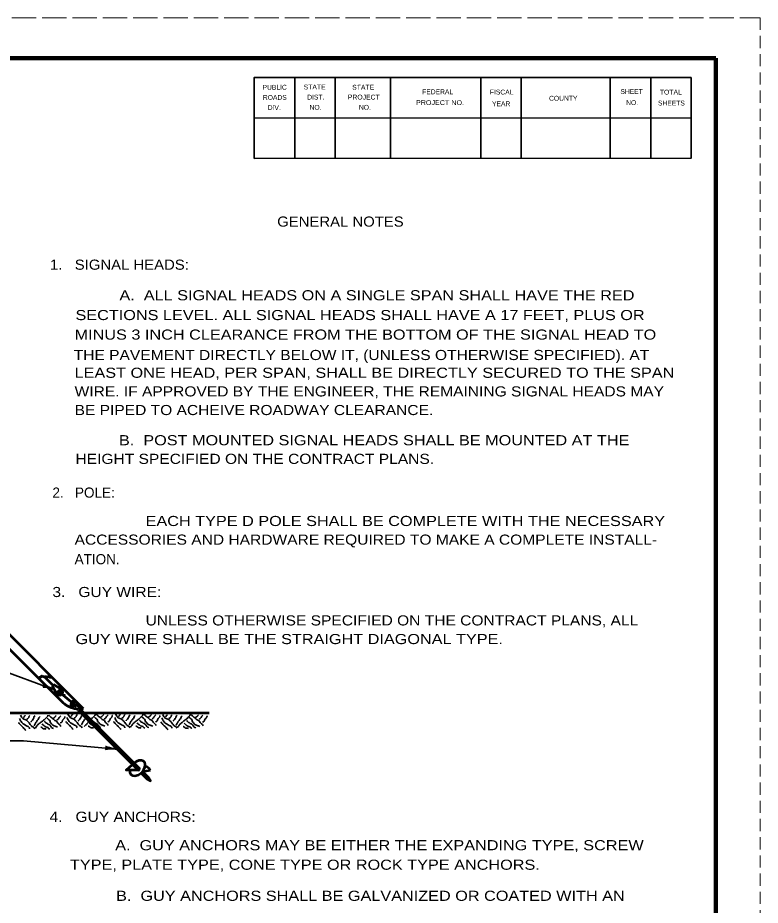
# Model space of a CAD drawing. Extents: x 12366 to 13046, y 9129 to 9570.
# Drawn here: x 12862.5 to 13046, y 9350.2 to 9569.5 of the extents above; entities that cross this region are included whole.
import ezdxf
from ezdxf.enums import TextEntityAlignment as Align

# ---------------------------------------------------------------- set-up
doc = ezdxf.new("R2010")
doc.units = 0
doc.linetypes.add('LONG_DASHED', pattern=[7.5, 6, -1.5])
doc.linetypes.add('MEDIUM_DASHED', pattern=[4.5, 3, -1.5])
doc.layers.add('1', color=7, linetype='Continuous', lineweight=53)
doc.layers.add('61', color=7, linetype='Continuous', lineweight=35)

msp = doc.modelspace()

# ---------------------------------------------------------------- linework, layer by layer
at = {"layer": '1', "linetype": 'MEDIUM_DASHED', "lineweight": 13}
msp.add_line((13046.012, 9569.533), (13045.992, 9129.513), dxfattribs=at)
at = {"layer": '1'}
for p, q in [((12856.715, 9420.771), (12878.635, 9398.851)), ((12858.482, 9415.468), (12873.332, 9400.618)), ((12869.026, 9406.73), (12871.147, 9404.608)), ((12870.971, 9404.431), (12871.324, 9404.785)), ((12872.031, 9402.664), (12870.971, 9404.431)), ((12873.092, 9403.724), (12871.324, 9404.785)), ((12873.269, 9403.901), (12871.854, 9402.487)), ((12872.208, 9402.133), (12871.854, 9402.487)), ((12873.622, 9403.548), (12872.208, 9402.133)), ((12876.155, 9400.064), (12872.886, 9402.807)), ((12873.622, 9403.548), (12873.269, 9403.901)), ((12873.411, 9402.367), (12874.148, 9402.023)), ((12876.892, 9399.316), (12876.737, 9399.895)), ((12722.941, 9397.801), (12909.771, 9397.801)), ((12876.892, 9399.316), (12876.312, 9399.471)), ((12877.771, 9398.801), (12892.621, 9383.951)), ((12893.328, 9383.244), (12895.297, 9383.592)), ((12893.328, 9383.244), (12894.742, 9381.83))]:
    msp.add_line(p, q, dxfattribs=at)
at = {"layer": '1', "lineweight": 35}
for p, q in [((12871.535, 9403.49), (12851.357, 9410.834)), ((12863.862, 9390.849), (12859.568, 9390.849)), ((12863.862, 9390.849), (12887.007, 9388.825))]:
    msp.add_line(p, q, dxfattribs=at)
at = {"layer": '1'}
for points in [[(12877.401, 9398.431), (12892.251, 9383.582), (12889.251, 9383.582), (12890.835, 9384.978)], [(12892.958, 9382.874), (12894.372, 9381.46), (12895.264, 9380.938), (12894.742, 9381.83)]]:
    msp.add_lwpolyline(points, dxfattribs=at)
for centre, radius, start, end in [((12872.867, 9402.889), 0.753, 230.20411, 39.79589), ((12877.601, 9404.587), 5.829, 222.90975, 254.56822), ((12876.449, 9399.76), 0.887, 22.37581, 247.62419), ((12876.397, 9399.811), 0.35, 13.9871, 256.0129), ((12875.1, 9399.33), 2.301, 358.69833, 19.49446), ((12876.974, 9401.556), 2.755, 251.74116, 268.96028), ((12876.28, 9397.482), 1.469, 40.24577, 64.00426), ((12878.72, 9399.922), 1.469, 205.99574, 229.75423), ((12877.601, 9404.587), 5.829, 272.0576, 280.22035), ((12892.237, 9383.965), 0.384, 272.04039, 357.95961), ((12893.536, 9382.47), 2.088, 32.48706, 78.42981)]:
    msp.add_arc(centre, radius, start, end, dxfattribs=at)
at = {"layer": '1', "lineweight": 40}
for centre, major_axis, ratio, start_param, end_param in [((12870.555, 9404.072), (-1.59, 0.766), 0.07063, 6.2823074, 8.5597026), ((12870.555, 9404.072), (-1.59, 0.766), 0.07063, 6.2823074, 8.5597026), ((12870.416, 9403.603), (1.731, -0.464), 0.122415, 0.8963533, 3.1415927), ((12870.416, 9403.603), (1.731, -0.464), 0.122415, 0.8963533, 3.1415927), ((12885.91, 9389.133), (-1.734, 0.328), 0.07063, 6.2823074, 8.5597026), ((12885.896, 9388.645), (1.793, 0), 0.122415, 0.8963533, 3.1415927)]:
    msp.add_ellipse(centre, major_axis=major_axis, ratio=ratio, start_param=start_param, end_param=end_param, dxfattribs=at)
at = {"layer": '1'}
msp.add_ellipse((12892.082, 9384.12), major_axis=(-1.599, -1.599), ratio=0.663245, start_param=5.5824837, end_param=10.8796755, dxfattribs=at)
msp.add_spline([(12867.675, 9406.275), (12867.902, 9406.611), (12868.036, 9406.498), (12868.304, 9406.766), (12868.448, 9406.9), (12868.778, 9406.766), (12869.201, 9406.704), (12869.418, 9406.735), (12869.727, 9406.56), (12869.892, 9406.755), (12870.222, 9406.642), (12870.521, 9406.56), (12870.857, 9406.629)], degree=3, dxfattribs=at)
at = {"layer": '1', "lineweight": 35}
for points in [[(12862.949, 9396.405), (12863.077, 9396.021), (12863.333, 9395.605), (12863.653, 9395.189), (12863.973, 9394.997), (12864.516, 9394.613), (12865.38, 9394.038), (12865.412, 9393.782)], [(12863.173, 9397.212), (12863.813, 9396.316), (12864.645, 9395.933), (12865.156, 9395.421), (12865.412, 9395.101), (12865.732, 9394.717), (12865.988, 9394.397), (12866.372, 9394.205), (12866.692, 9393.821)], [(12864.325, 9397.14), (12864.229, 9397.012), (12864.197, 9397.012), (12864.133, 9396.949), (12863.973, 9396.661), (12863.941, 9396.597)], [(12865.508, 9397.109), (12865.316, 9396.949), (12865.252, 9396.789), (12865.188, 9396.597), (12865.06, 9396.469), (12864.996, 9396.405), (12864.708, 9396.181)], [(12866.756, 9397.013), (12866.564, 9396.821), (12866.436, 9396.501), (12866.276, 9396.181), (12865.924, 9395.797), (12865.796, 9395.605), (12865.732, 9395.509)], [(12868.003, 9396.821), (12867.715, 9396.501), (12867.556, 9396.149), (12867.3, 9395.861), (12867.108, 9395.573), (12866.916, 9395.349), (12866.82, 9395.125), (12866.692, 9394.901), (12866.532, 9394.581)], [(12869.923, 9397.212), (12869.923, 9397.084), (12869.859, 9396.892), (12869.731, 9396.764), (12869.603, 9396.636), (12869.347, 9396.38), (12869.155, 9396.189), (12868.579, 9395.741), (12868.259, 9395.485), (12867.619, 9394.973), (12867.363, 9394.717), (12867.236, 9394.525), (12867.044, 9394.269), (12866.852, 9393.949)], [(12869.091, 9395.733), (12869.571, 9395.253), (12869.667, 9395.221), (12869.763, 9395.125), (12870.179, 9394.869), (12870.69, 9394.421), (12870.85, 9394.165), (12871.33, 9393.878)], [(12869.731, 9396.437), (12869.923, 9396.309), (12870.115, 9396.149), (12870.467, 9395.701), (12870.498, 9395.413), (12870.754, 9395.189), (12870.85, 9395.029), (12871.49, 9394.549), (12871.874, 9394.421), (12871.97, 9394.357), (12872.322, 9394.198)], [(12870.147, 9397.18), (12870.658, 9396.732), (12871.106, 9396.348), (12871.874, 9395.773), (12872.066, 9395.709), (12872.258, 9395.453), (12872.578, 9395.069), (12872.962, 9394.685), (12873.154, 9394.429)], [(12871.298, 9396.469), (12871.746, 9396.789), (12871.842, 9396.916), (12872.002, 9397.14)], [(12872.162, 9396.021), (12872.514, 9396.277), (12872.738, 9396.597), (12872.802, 9396.693), (12872.93, 9396.821), (12873.122, 9397.044)], [(12872.994, 9395.285), (12873.441, 9395.541), (12873.505, 9395.829), (12873.921, 9396.341), (12874.049, 9396.501), (12874.113, 9396.757), (12874.145, 9396.885)], [(12874.409, 9395.629), (12874.537, 9395.405), (12874.793, 9395.149), (12875.112, 9394.765), (12875.4, 9394.573), (12875.656, 9394.253), (12875.912, 9393.997), (12876.168, 9393.677)], [(12874.665, 9396.652), (12874.793, 9396.268), (12875.048, 9395.852), (12875.368, 9395.437), (12875.688, 9395.245), (12876.232, 9394.861), (12877.096, 9394.285), (12877.128, 9394.029)], [(12874.889, 9397.46), (12875.528, 9396.564), (12876.36, 9396.18), (12876.872, 9395.668), (12877.128, 9395.348), (12877.448, 9394.965), (12877.704, 9394.645), (12878.087, 9394.453), (12878.407, 9394.069)], [(12876.04, 9397.388), (12875.944, 9397.26), (12875.912, 9397.26), (12875.848, 9397.196), (12875.688, 9396.908), (12875.656, 9396.844)], [(12877.224, 9397.356), (12877.032, 9397.196), (12876.968, 9397.036), (12876.904, 9396.844), (12876.776, 9396.716), (12876.712, 9396.652), (12876.424, 9396.428)], [(12878.471, 9397.26), (12878.279, 9397.068), (12878.151, 9396.748), (12877.992, 9396.428), (12877.64, 9396.044), (12877.512, 9395.852), (12877.448, 9395.757)], [(12879.233, 9396.353), (12879.015, 9396.108), (12878.823, 9395.82), (12878.631, 9395.597), (12878.535, 9395.373), (12878.407, 9395.149), (12878.247, 9394.829)], [(12879.885, 9395.624), (12879.885, 9395.496), (12879.821, 9395.304), (12879.693, 9395.176), (12879.565, 9395.048), (12879.309, 9394.792), (12879.117, 9394.6), (12878.865, 9394.404)], [(12881.638, 9397.46), (12881.638, 9397.332), (12881.574, 9397.14), (12881.446, 9397.012), (12881.318, 9396.884), (12881.062, 9396.628), (12880.87, 9396.436), (12880.619, 9396.24)], [(12880.807, 9395.98), (12881.286, 9395.501), (12881.382, 9395.469), (12881.478, 9395.373), (12881.894, 9395.117), (12882.406, 9394.669), (12882.566, 9394.413), (12883.046, 9394.125)], [(12881.446, 9396.684), (12881.638, 9396.556), (12881.83, 9396.396), (12882.182, 9395.948), (12882.214, 9395.661), (12882.47, 9395.437), (12882.566, 9395.277), (12883.206, 9394.797), (12883.59, 9394.669), (12883.686, 9394.605), (12884.037, 9394.445)], [(12881.862, 9397.428), (12882.374, 9396.98), (12882.822, 9396.596), (12883.59, 9396.02), (12883.781, 9395.956), (12883.974, 9395.7), (12884.293, 9395.316), (12884.677, 9394.932), (12884.869, 9394.677)], [(12883.014, 9396.716), (12883.462, 9397.036), (12883.558, 9397.164), (12883.718, 9397.388)], [(12883.877, 9396.268), (12884.229, 9396.524), (12884.453, 9396.844), (12884.517, 9396.94), (12884.645, 9397.068), (12884.837, 9397.292)], [(12884.709, 9395.533), (12885.157, 9395.789), (12885.221, 9396.076), (12885.637, 9396.588), (12885.765, 9396.748), (12885.829, 9397.004), (12885.861, 9397.132)], [(12886.207, 9395.629), (12886.335, 9395.405), (12886.591, 9395.149), (12886.91, 9394.765), (12887.198, 9394.573), (12887.454, 9394.253), (12887.71, 9393.997), (12887.966, 9393.677)], [(12886.463, 9396.652), (12886.591, 9396.268), (12886.846, 9395.852), (12887.166, 9395.437), (12887.486, 9395.245), (12888.03, 9394.861), (12888.894, 9394.285), (12888.926, 9394.029)], [(12886.687, 9397.46), (12887.326, 9396.564), (12888.158, 9396.18), (12888.67, 9395.668), (12888.926, 9395.348), (12889.246, 9394.965), (12889.502, 9394.645), (12889.886, 9394.453), (12890.205, 9394.069)], [(12887.838, 9397.388), (12887.742, 9397.26), (12887.71, 9397.26), (12887.646, 9397.196), (12887.486, 9396.908), (12887.454, 9396.844)], [(12889.022, 9397.356), (12888.83, 9397.196), (12888.766, 9397.036), (12888.702, 9396.844), (12888.574, 9396.716), (12888.51, 9396.652), (12888.222, 9396.428)], [(12890.269, 9397.26), (12890.077, 9397.068), (12889.949, 9396.748), (12889.789, 9396.428), (12889.438, 9396.044), (12889.31, 9395.852), (12889.246, 9395.757)], [(12891.517, 9397.068), (12891.229, 9396.748), (12891.069, 9396.396), (12890.813, 9396.108), (12890.621, 9395.82), (12890.429, 9395.597), (12890.333, 9395.373), (12890.205, 9395.149), (12890.045, 9394.829)], [(12893.436, 9397.46), (12893.436, 9397.332), (12893.372, 9397.14), (12893.244, 9397.012), (12893.116, 9396.884), (12892.86, 9396.628), (12892.668, 9396.436), (12892.093, 9395.988), (12891.773, 9395.732), (12891.133, 9395.22), (12890.877, 9394.965), (12890.749, 9394.773), (12890.557, 9394.517), (12890.365, 9394.197)], [(12892.605, 9395.98), (12893.084, 9395.501), (12893.18, 9395.469), (12893.276, 9395.373), (12893.692, 9395.117), (12894.204, 9394.669), (12894.364, 9394.413), (12894.844, 9394.125)], [(12893.244, 9396.684), (12893.436, 9396.556), (12893.628, 9396.396), (12893.98, 9395.948), (12894.012, 9395.661), (12894.268, 9395.437), (12894.364, 9395.277), (12895.004, 9394.797), (12895.388, 9394.669), (12895.484, 9394.605), (12895.835, 9394.445)], [(12893.66, 9397.428), (12894.172, 9396.98), (12894.62, 9396.596), (12895.388, 9396.02), (12895.579, 9395.956), (12895.771, 9395.7), (12896.091, 9395.316), (12896.475, 9394.932), (12896.667, 9394.677)], [(12894.812, 9396.716), (12895.26, 9397.036), (12895.356, 9397.164), (12895.516, 9397.388)], [(12895.675, 9396.268), (12896.027, 9396.524), (12896.251, 9396.844), (12896.315, 9396.94), (12896.443, 9397.068), (12896.635, 9397.292)], [(12896.507, 9395.533), (12896.955, 9395.789), (12897.019, 9396.076), (12897.435, 9396.588), (12897.563, 9396.748), (12897.627, 9397.004), (12897.659, 9397.132)], [(12897.84, 9395.546), (12897.968, 9395.322), (12898.224, 9395.066), (12898.544, 9394.682), (12898.832, 9394.49), (12899.087, 9394.171), (12899.343, 9393.915), (12899.599, 9393.595)], [(12898.096, 9396.57), (12898.224, 9396.186), (12898.48, 9395.77), (12898.799, 9395.354), (12899.119, 9395.162), (12899.663, 9394.778), (12900.527, 9394.202), (12900.559, 9393.947)], [(12898.32, 9397.377), (12898.959, 9396.481), (12899.791, 9396.098), (12900.303, 9395.586), (12900.559, 9395.266), (12900.879, 9394.882), (12901.135, 9394.562), (12901.519, 9394.37), (12901.838, 9393.986)], [(12899.471, 9397.306), (12899.375, 9397.177), (12899.343, 9397.177), (12899.279, 9397.113), (12899.119, 9396.826), (12899.087, 9396.762)], [(12900.655, 9397.273), (12900.463, 9397.113), (12900.399, 9396.954), (12900.335, 9396.762), (12900.207, 9396.634), (12900.143, 9396.57), (12899.855, 9396.346)], [(12901.902, 9397.178), (12901.71, 9396.986), (12901.583, 9396.666), (12901.423, 9396.346), (12901.071, 9395.962), (12900.943, 9395.77), (12900.879, 9395.674)], [(12903.15, 9396.986), (12902.862, 9396.666), (12902.702, 9396.314), (12902.446, 9396.026), (12902.254, 9395.738), (12902.062, 9395.514), (12901.966, 9395.29), (12901.838, 9395.066), (12901.678, 9394.746)], [(12905.069, 9397.377), (12905.069, 9397.249), (12905.005, 9397.057), (12904.877, 9396.929), (12904.749, 9396.801), (12904.493, 9396.545), (12904.302, 9396.353), (12903.726, 9395.906), (12903.406, 9395.65), (12902.766, 9395.138), (12902.51, 9394.882), (12902.382, 9394.69), (12902.19, 9394.434), (12901.998, 9394.114)], [(12904.238, 9395.898), (12904.717, 9395.418), (12904.813, 9395.386), (12904.909, 9395.29), (12905.325, 9395.034), (12905.837, 9394.586), (12905.997, 9394.331), (12906.477, 9394.043)], [(12904.877, 9396.602), (12905.069, 9396.474), (12905.261, 9396.314), (12905.613, 9395.866), (12905.645, 9395.578), (12905.901, 9395.354), (12905.997, 9395.194), (12906.637, 9394.714), (12907.021, 9394.586), (12907.117, 9394.522), (12907.468, 9394.362)], [(12905.293, 9397.345), (12905.805, 9396.897), (12906.253, 9396.513), (12907.021, 9395.938), (12907.213, 9395.874), (12907.405, 9395.618), (12907.724, 9395.234), (12908.108, 9394.85), (12908.3, 9394.594)], [(12906.445, 9396.634), (12906.893, 9396.954), (12906.989, 9397.082), (12907.149, 9397.306)], [(12907.309, 9396.186), (12907.66, 9396.442), (12907.884, 9396.762), (12907.948, 9396.858), (12908.076, 9396.986), (12908.268, 9397.209)], [(12908.14, 9395.45), (12908.588, 9395.706), (12908.652, 9395.994), (12909.068, 9396.506), (12909.196, 9396.666), (12909.26, 9396.922), (12909.292, 9397.05)], [(12862.693, 9395.381), (12862.821, 9395.157), (12863.077, 9394.901), (12863.397, 9394.517), (12863.685, 9394.325), (12863.941, 9394.005), (12864.197, 9393.75), (12864.452, 9393.43)], [(12868.195, 9394.261), (12868.419, 9394.133), (12868.835, 9393.846), (12868.899, 9393.814), (12869.091, 9393.814), (12869.507, 9393.75)], [(12868.483, 9395.029), (12868.899, 9394.645), (12869.059, 9394.517), (12869.347, 9394.325), (12869.923, 9394.101), (12870.115, 9393.878), (12870.403, 9393.75)], [(12879.911, 9394.509), (12880.135, 9394.381), (12880.551, 9394.093), (12880.615, 9394.061), (12880.807, 9394.061), (12881.222, 9393.997)], [(12880.199, 9395.277), (12880.615, 9394.893), (12880.775, 9394.765), (12880.989, 9394.622)], [(12891.709, 9394.509), (12891.933, 9394.381), (12892.349, 9394.093), (12892.413, 9394.061), (12892.605, 9394.061), (12893.02, 9393.997)], [(12891.997, 9395.277), (12892.413, 9394.893), (12892.573, 9394.765), (12892.86, 9394.573), (12893.436, 9394.349), (12893.628, 9394.125), (12893.916, 9393.997)], [(12903.342, 9394.426), (12903.566, 9394.298), (12903.982, 9394.011), (12904.046, 9393.979), (12904.238, 9393.979), (12904.654, 9393.915)], [(12903.63, 9395.194), (12904.046, 9394.81), (12904.206, 9394.682), (12904.493, 9394.49), (12905.069, 9394.266), (12905.261, 9394.043), (12905.549, 9393.915)]]:
    msp.add_spline(points, degree=3, dxfattribs=at)
at = {"layer": '61', "linetype": 'LONG_DASHED', "lineweight": 13}
msp.add_line((12365.992, 9569.533), (13046.012, 9569.533), dxfattribs=at)
at = {"layer": '61', "lineweight": 158}
msp.add_line((13035.032, 9559.533), (13035.052, 9139.493), dxfattribs=at)
at = {"layer": '61'}
for p, q in [((12930.952, 9554.773), (12930.952, 9534.773)), ((12940.952, 9554.773), (12940.952, 9534.773)), ((12954.632, 9554.773), (12954.632, 9534.773)), ((12976.952, 9554.773), (12976.952, 9534.773)), ((12986.952, 9554.773), (12986.952, 9534.773)), ((13008.932, 9554.793), (13008.932, 9534.793)), ((13018.932, 9554.793), (13018.932, 9534.793)), ((13028.952, 9544.753), (12920.932, 9544.773))]:
    msp.add_line(p, q, dxfattribs=at)
at = {"layer": '61', "lineweight": 158}
msp.add_lwpolyline([(13035.032, 9559.533), (12395.992, 9559.533), (12395.992, 9139.513)], dxfattribs=at)
at = {"layer": '61'}
for points in [[(13028.932, 9554.793), (12920.952, 9554.773), (12920.952, 9534.773)], [(13028.932, 9554.793), (13028.932, 9534.793), (12920.952, 9534.773)]]:
    msp.add_lwpolyline(points, dxfattribs=at)

# ---------------------------------------------------------------- texts
at = {"layer": '1', "width": 1.1}
msp.add_text('GENERAL NOTES', height=2.5, dxfattribs=at).set_placement((12942.244, 9517.915), align=Align.CENTER)
at = {"layer": '1'}
for s, width, p in [('1.   SIGNAL HEADS:', 1.1, (12870.441, 9507.265)), ('A.  ALL SIGNAL HEADS ON A SINGLE SPAN SHALL HAVE THE RED ', 1.2, (12887.618, 9499.707)), ('SECTIONS LEVEL. ALL SIGNAL HEADS SHALL HAVE A 17 FEET, PLUS OR ', 1.2, (12876.752, 9494.816)), ('MINUS 3 INCH CLEARANCE FROM THE BOTTOM OF THE SIGNAL HEAD TO', 1.2, (12876.533, 9489.99)), ('THE PAVEMENT DIRECTLY BELOW IT, (UNLESS OTHERWISE SPECIFIED). AT ', 1.15, (12876.313, 9484.944)), ('LEAST ONE HEAD, PER SPAN, SHALL BE DIRECTLY SECURED TO THE SPAN ', 1.2, (12876.533, 9480.557)), ('WIRE. IF APPROVED BY THE ENGINEER, THE REMAINING SIGNAL HEADS MAY ', 1.15, (12876.533, 9475.951)), ('BE PIPED TO ACHEIVE ROADWAY CLEARANCE.', 1.15, (12876.533, 9471.344)), ('B.  POST MOUNTED SIGNAL HEADS SHALL BE MOUNTED AT THE', 1.2, (12887.5, 9463.886)), ('HEIGHT SPECIFIED ON THE CONTRACT PLANS.', 1.15, (12876.752, 9459.28)), ('EACH TYPE D POLE SHALL BE COMPLETE WITH THE NECESSARY', 1.2, (12894.081, 9443.925)), ('ACCESSORIES AND HARDWARE REQUIRED TO MAKE A COMPLETE INSTALL-', 1.15, (12876.533, 9439.318)), ('3.   GUY WIRE:', 1.15, (12871.049, 9426.376)), ('UNLESS OTHERWISE SPECIFIED ON THE CONTRACT PLANS, ALL', 1.15, (12894.081, 9419.357)), ('GUY WIRE SHALL BE THE STRAIGHT DIAGONAL TYPE.', 1.2, (12876.752, 9414.75)), ('4.   GUY ANCHORS:', 1.15, (12870.339, 9370.828)), ('A.  GUY ANCHORS MAY BE EITHER THE EXPANDING TYPE, SCREW', 1.2, (12886.571, 9363.808)), ('TYPE, PLATE TYPE, CONE TYPE OR ROCK TYPE ANCHORS.', 1.2, (12875.384, 9358.982)), ('B.  GUY ANCHORS SHALL BE GALVANIZED OR COATED WITH AN ', 1.2, (12886.791, 9351.305))]:
    msp.add_text(s, height=2.5, dxfattribs=dict(at, width=width)).set_placement(p)
for s, p in [('2.   POLE:', (12871.049, 9450.944)), ('ATION.', (12876.533, 9434.492))]:
    msp.add_text(s, height=2.5, dxfattribs=at).set_placement(p)
at = {"layer": '61'}
for s, rotation, p in [('PUBLIC', 0.033, (12922.992, 9551.753)), ('FEDERAL', 0.007, (12962.452, 9550.633)), ('FISCAL', 359.942, (12979.192, 9550.573)), ('SHEET', 0.059, (13011.452, 9550.693)), ('ROADS', 0.124, (12923.072, 9549.233)), ('DIST.', 0.056, (12934.032, 9549.313)), ('COUNTY', 0.069, (12993.812, 9549.033)), ('SHEETS', 359.959, (13020.732, 9547.853)), ('DIV.', 359.932, (12924.272, 9546.733)), ('YEAR', 0.105, (12979.712, 9547.673))]:
    msp.add_text(s, height=1.201, rotation=rotation, dxfattribs=at).set_placement(p)
for s, rotation, width, p in [('STATE', 0.059, 1.05, (12933.152, 9551.813)), ('STATE', 0.059, 1.05, (12945.152, 9551.753)), ('TOTAL', 359.926, 1.05, (13021.192, 9550.553)), ('PROJECT', 359.908, 1.05, (12944.072, 9549.333)), ('PROJECT NO.', 359.922, 1.1, (12960.912, 9547.973)), ('NO.', 359.852, 0.95, (13012.872, 9547.973)), ('NO.', 359.852, 0.95, (12934.612, 9546.793)), ('NO.', 0.225, 0.95, (12946.812, 9546.793))]:
    msp.add_text(s, height=1.201, rotation=rotation, dxfattribs=dict(at, width=width)).set_placement(p)

doc.saveas('drawing.dxf')
